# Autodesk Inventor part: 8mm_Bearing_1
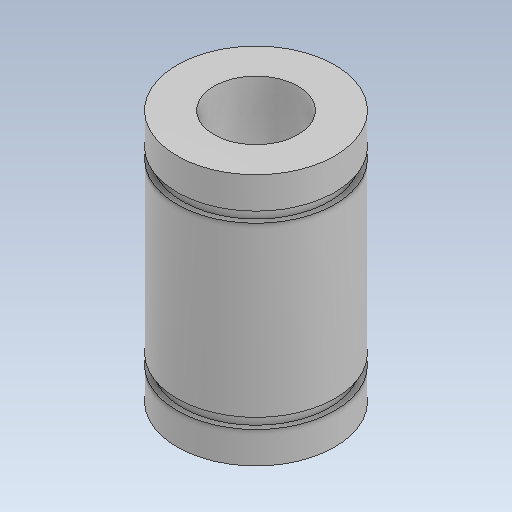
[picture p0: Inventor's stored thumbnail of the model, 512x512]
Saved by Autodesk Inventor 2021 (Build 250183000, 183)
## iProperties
Created: 2026-10
Part Number: 8mm_Bearing_1
Material: Generic
Document SubType Name: Modeling
Designer: hp
Density: 1 g/cm^3
Appearance: Default
Author: hp
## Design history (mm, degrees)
feature "Body1"
body "Solid1"
